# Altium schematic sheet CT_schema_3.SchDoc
size 398 x 269 mm
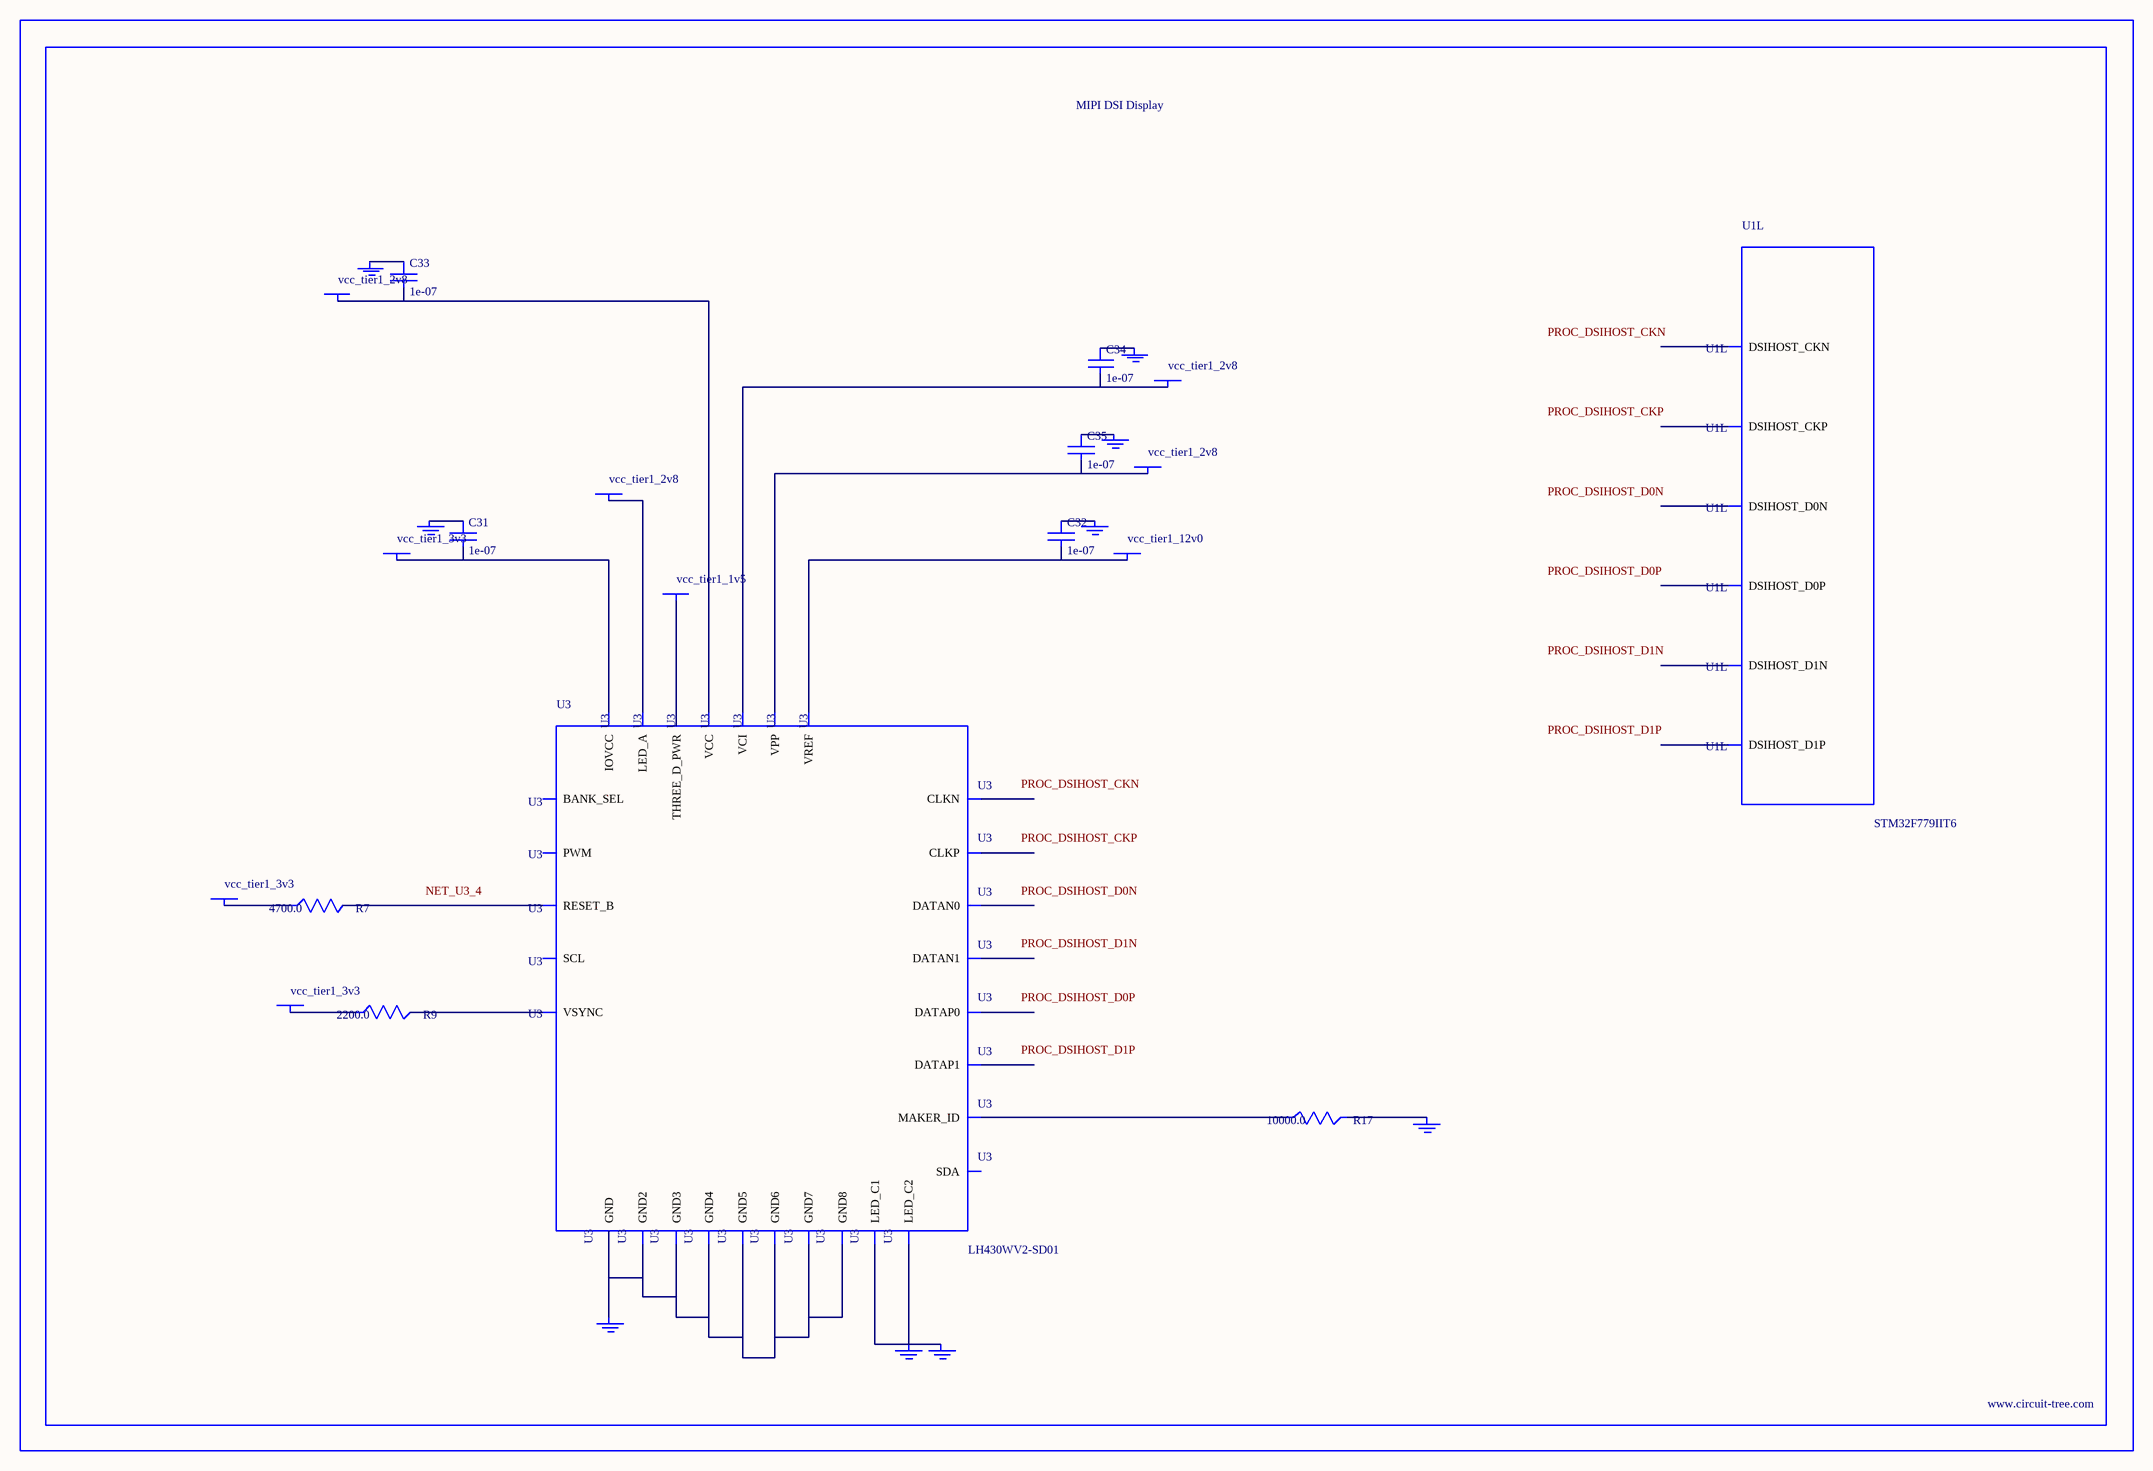
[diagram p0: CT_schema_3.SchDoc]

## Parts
BORDER2  (no value)
C31  1e-07  [C0402]
C32  1e-07  [C0402]
C33  1e-07  [C0402]
C34  1e-07  [C0402]
C35  1e-07  [C0402]
GND_INSTANCE_2_0  (no value)
GND_INSTANCE_2_1  (no value)
GND_INSTANCE_2_2  (no value)
GND_INSTANCE_2_3  (no value)
GND_INSTANCE_2_4  (no value)
GND_INSTANCE_2_5  (no value)
GND_INSTANCE_2_6  (no value)
GND_INSTANCE_2_7  (no value)
GND_INSTANCE_2_8  (no value)
POWER_INSTANCE_2_0  vcc_tier1_3v3
POWER_INSTANCE_2_1  vcc_tier1_2v8
POWER_INSTANCE_2_2  vcc_tier1_2v8
POWER_INSTANCE_2_3  vcc_tier1_2v8
POWER_INSTANCE_2_4  vcc_tier1_2v8
POWER_INSTANCE_2_5  vcc_tier1_12v0
POWER_INSTANCE_2_6  vcc_tier1_3v3
POWER_INSTANCE_2_7  vcc_tier1_3v3
POWER_INSTANCE_2_8  vcc_tier1_1v5
R7  4700.0  [R0603]
R9  2200.0  [R0603]
R17  10000.0  [R0603]
U1  STM32F779IIT6  [LQFP176]  (part L of 14)
U3  LH430WV2-SD01  [LH430WV2-SD01]

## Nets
NetC31_1: C31.1 GND_INSTANCE_2_0.0(GND)
NetC31_2: C31.2 POWER_INSTANCE_2_0.0(PWR) U3.2(IOVCC)
NetC32_1: C32.1 GND_INSTANCE_2_7.0(GND)
NetC32_2: C32.2 POWER_INSTANCE_2_5.0(PWR) U3.30(VREF)
NetC33_1: C33.1 GND_INSTANCE_2_5.0(GND)
NetC33_2: C33.2 POWER_INSTANCE_2_3.0(PWR) U3.22(VCC)
NetC34_1: C34.1 GND_INSTANCE_2_4.0(GND)
NetC34_2: C34.2 POWER_INSTANCE_2_2.0(PWR) U3.21(VCI)
NetC35_1: C35.1 GND_INSTANCE_2_6.0(GND)
NetC35_2: C35.2 POWER_INSTANCE_2_4.0(PWR) U3.23(VPP)
NetGND_INSTANCE_2_1_0: GND_INSTANCE_2_1.0(GND) GND_INSTANCE_2_2.0(GND) U3.17(LED_C1) U3.18(LED_C2)
NetGND_INSTANCE_2_3_0: GND_INSTANCE_2_3.0(GND) R17.2
NetGND_INSTANCE_2_8_0: GND_INSTANCE_2_8.0(GND) U3.1(GND) U3.6(GND2) U3.9(GND3) U3.12(GND4) U3.15(GND5) U3.19(GND6) U3.24(GND7) U3.27(GND8)
NetPOWER_INSTANCE_2_1_0: POWER_INSTANCE_2_1.0(PWR) U3.16(LED_A)
NetPOWER_INSTANCE_2_6_0: POWER_INSTANCE_2_6.0(PWR) R7.1
NetPOWER_INSTANCE_2_7_0: POWER_INSTANCE_2_7.0(PWR) R9.1
NetPOWER_INSTANCE_2_8_0: POWER_INSTANCE_2_8.0(PWR) U3.29(THREE_D_PWR)
NetR7_2: R7.2 U3.4(RESET_B)
NetR9_2: R9.2 U3.5(VSYNC)
NetR17_1: R17.1 U3.20(MAKER_ID)

Not connected (* = marked no-connect by the designer): U1 101(DSIHOST_D0P) 102(DSIHOST_D0N) 104(DSIHOST_CKP) 105(DSIHOST_CKN) 107(DSIHOST_D1P) 108(DSIHOST_D1N); U3 3(PWM) 7(DATAN0) 8(DATAP0) 10(DATAN1) 11(DATAP1) 13(CLKN) 14(CLKP) 25(SCL) 26(SDA) 28(BANK_SEL)

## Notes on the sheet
- Labels drawn without touching a wire or pin: NET_U3_4, PROC_DSIHOST_CKN, PROC_DSIHOST_CKP, PROC_DSIHOST_D0N, PROC_DSIHOST_D0P, PROC_DSIHOST_D1N, PROC_DSIHOST_D1P

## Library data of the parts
BORDER2 = BORDER_PAGE2
C31-C35 = C0402C104K3RACTU
GND_INSTANCE_2_0-GND_INSTANCE_2_8 = GND
POWER_INSTANCE_2_0-POWER_INSTANCE_2_8 = PWR
R7 = RC0603JR-074K7L
R9 = RC0603JR-072K2L
R17 = RC0603JR-0710KL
